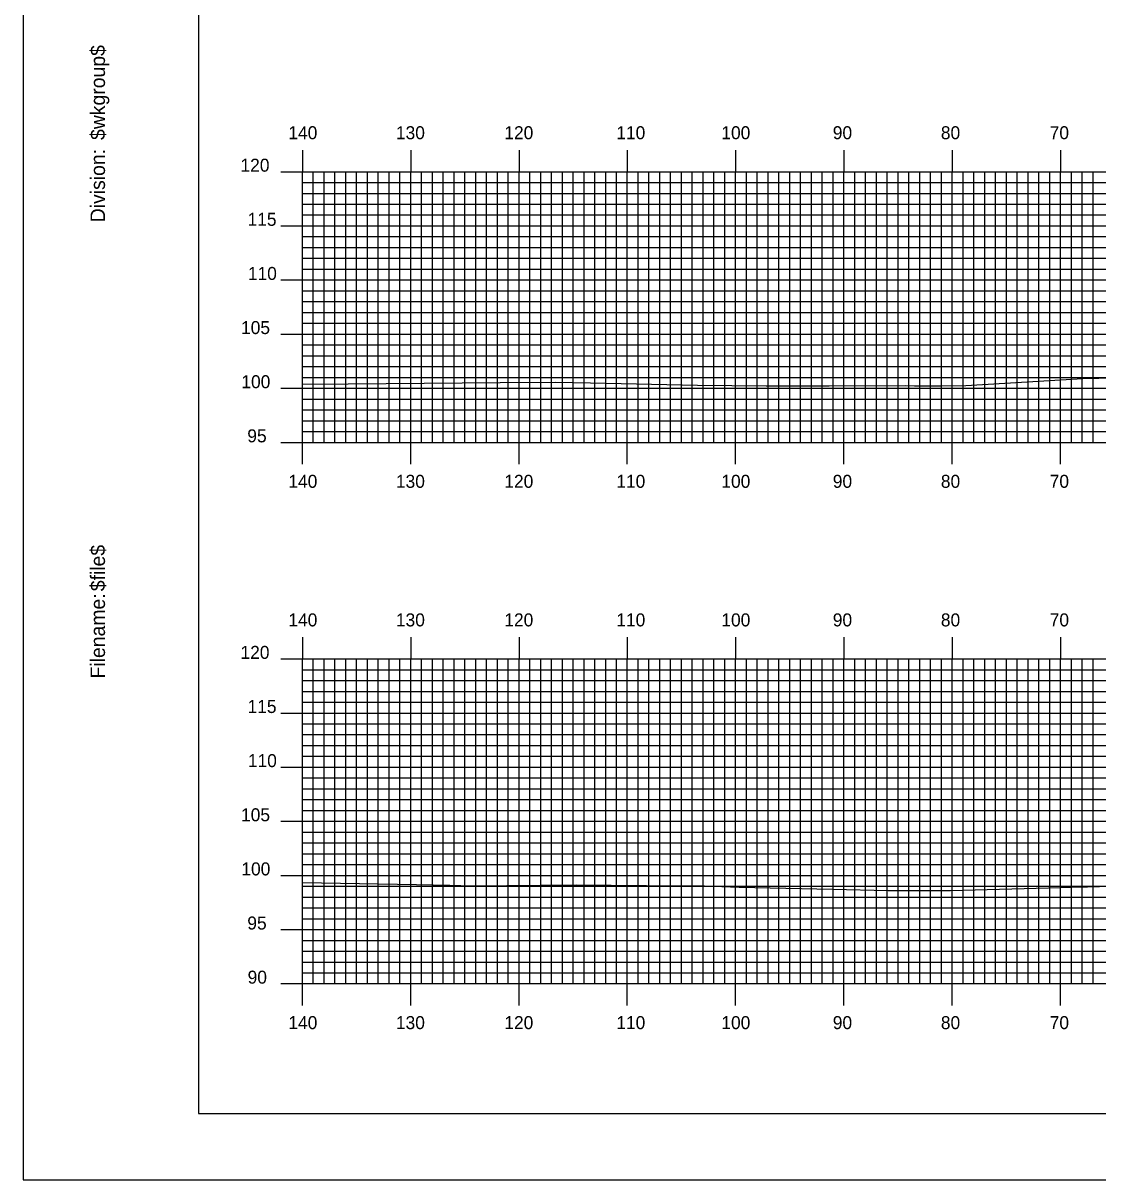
# Model space of a CAD drawing. Extents: x 1787763 to 1788106, y 442591 to 442811.
# Drawn here: x 1787762.8 to 1787862.1, y 442590.5 to 442697.4 of the extents above; entities that cross this region are included whole.
import ezdxf

# ---------------------------------------------------------------- set-up
doc = ezdxf.new("R2010")
doc.units = 0
for name, color, linetype in [('BORDER', 7, 'Continuous'), ('H_V ANNOTATION', 7, 'Continuous'), ('MAJOR', 7, 'Continuous'), ('MINOR', 7, 'Continuous'), ('PLOT BOUNDARY', 7, 'Continuous'), ('S_Roadway_Centerline', 7, 'Continuous')]:
    doc.layers.add(name, color=color, linetype=linetype)

msp = doc.modelspace()

# ---------------------------------------------------------------- linework, layer by layer
at = {"layer": 'BORDER'}
msp.add_lwpolyline([(1787779.02, 442596.67), (1788099.02, 442596.67), (1788099.02, 442806.67), (1787779.02, 442806.67)], close=True, dxfattribs=at)
at = {"layer": 'MAJOR'}
for p, q in [((1787788.62, 442685.67), (1787788.62, 442683.67)), ((1787798.62, 442685.67), (1787798.62, 442683.67)), ((1787808.62, 442685.67), (1787808.62, 442683.67)), ((1787818.62, 442685.67), (1787818.62, 442683.67)), ((1787828.62, 442685.67), (1787828.62, 442683.67)), ((1787838.62, 442685.67), (1787838.62, 442683.67)), ((1787848.62, 442685.67), (1787848.62, 442683.67)), ((1787858.62, 442685.67), (1787858.62, 442683.67)), ((1787786.61, 442683.67), (1787788.62, 442683.67)), ((1787788.62, 442683.67), (1788068.62, 442683.67)), ((1787788.62, 442658.67), (1787788.62, 442683.67)), ((1787788.62, 442658.67), (1787788.62, 442683.67)), ((1787788.62, 442683.67), (1788068.62, 442683.67)), ((1787798.62, 442658.67), (1787798.62, 442683.67)), ((1787808.62, 442658.67), (1787808.62, 442683.67)), ((1787818.62, 442658.67), (1787818.62, 442683.67)), ((1787828.62, 442658.67), (1787828.62, 442683.67)), ((1787838.62, 442658.67), (1787838.62, 442683.67)), ((1787848.62, 442658.67), (1787848.62, 442683.67)), ((1787858.62, 442658.67), (1787858.62, 442683.67)), ((1787786.61, 442678.67), (1787788.62, 442678.67)), ((1787788.62, 442678.67), (1788068.62, 442678.67)), ((1787786.61, 442673.67), (1787788.62, 442673.67)), ((1787788.62, 442673.67), (1788068.62, 442673.67)), ((1787786.61, 442668.67), (1787788.62, 442668.67)), ((1787788.62, 442668.67), (1788068.62, 442668.67)), ((1787786.61, 442663.67), (1787788.62, 442663.67)), ((1787788.62, 442663.67), (1788068.62, 442663.67)), ((1787786.61, 442658.67), (1787788.62, 442658.67)), ((1787788.62, 442658.67), (1788068.62, 442658.67)), ((1787788.62, 442658.67), (1788068.62, 442658.67)), ((1787788.62, 442656.66), (1787788.62, 442658.67)), ((1787798.62, 442656.66), (1787798.62, 442658.67)), ((1787808.62, 442656.66), (1787808.62, 442658.67)), ((1787818.62, 442656.66), (1787818.62, 442658.67)), ((1787828.62, 442656.66), (1787828.62, 442658.67)), ((1787838.62, 442656.66), (1787838.62, 442658.67)), ((1787848.62, 442656.66), (1787848.62, 442658.67)), ((1787858.62, 442656.66), (1787858.62, 442658.67)), ((1787788.62, 442640.67), (1787788.62, 442638.67)), ((1787798.62, 442640.67), (1787798.62, 442638.67)), ((1787808.62, 442640.67), (1787808.62, 442638.67)), ((1787818.62, 442640.67), (1787818.62, 442638.67)), ((1787828.62, 442640.67), (1787828.62, 442638.67)), ((1787838.62, 442640.67), (1787838.62, 442638.67)), ((1787848.62, 442640.67), (1787848.62, 442638.67)), ((1787858.62, 442640.67), (1787858.62, 442638.67)), ((1787786.61, 442638.67), (1787788.62, 442638.67)), ((1787788.62, 442638.67), (1788068.62, 442638.67)), ((1787788.62, 442608.67), (1787788.62, 442638.67)), ((1787788.62, 442608.67), (1787788.62, 442638.67)), ((1787788.62, 442638.67), (1788068.62, 442638.67)), ((1787798.62, 442608.67), (1787798.62, 442638.67)), ((1787808.62, 442608.67), (1787808.62, 442638.67)), ((1787818.62, 442608.67), (1787818.62, 442638.67)), ((1787828.62, 442608.67), (1787828.62, 442638.67)), ((1787838.62, 442608.67), (1787838.62, 442638.67)), ((1787848.62, 442608.67), (1787848.62, 442638.67)), ((1787858.62, 442608.67), (1787858.62, 442638.67)), ((1787786.61, 442633.67), (1787788.62, 442633.67)), ((1787788.62, 442633.67), (1788068.62, 442633.67)), ((1787786.61, 442628.67), (1787788.62, 442628.67)), ((1787788.62, 442628.67), (1788068.62, 442628.67)), ((1787786.61, 442623.67), (1787788.62, 442623.67)), ((1787788.62, 442623.67), (1788068.62, 442623.67)), ((1787786.61, 442618.67), (1787788.62, 442618.67)), ((1787788.62, 442618.67), (1788068.62, 442618.67)), ((1787786.61, 442613.67), (1787788.62, 442613.67)), ((1787788.62, 442613.67), (1788068.62, 442613.67)), ((1787786.61, 442608.67), (1787788.62, 442608.67)), ((1787788.62, 442608.67), (1788068.62, 442608.67)), ((1787788.62, 442608.67), (1788068.62, 442608.67)), ((1787788.62, 442606.66), (1787788.62, 442608.67)), ((1787798.62, 442606.66), (1787798.62, 442608.67)), ((1787808.62, 442606.66), (1787808.62, 442608.67)), ((1787818.62, 442606.66), (1787818.62, 442608.67)), ((1787828.62, 442606.66), (1787828.62, 442608.67)), ((1787838.62, 442606.66), (1787838.62, 442608.67)), ((1787848.62, 442606.66), (1787848.62, 442608.67)), ((1787858.62, 442606.66), (1787858.62, 442608.67))]:
    msp.add_line(p, q, dxfattribs=at)
at = {"layer": 'MINOR'}
for p, q in [((1787789.62, 442658.67), (1787789.62, 442683.67)), ((1787790.62, 442658.67), (1787790.62, 442683.67)), ((1787791.62, 442658.67), (1787791.62, 442683.67)), ((1787792.62, 442658.67), (1787792.62, 442683.67)), ((1787793.62, 442658.67), (1787793.62, 442683.67)), ((1787794.62, 442658.67), (1787794.62, 442683.67)), ((1787795.62, 442658.67), (1787795.62, 442683.67)), ((1787796.62, 442658.67), (1787796.62, 442683.67)), ((1787797.62, 442658.67), (1787797.62, 442683.67)), ((1787799.62, 442658.67), (1787799.62, 442683.67)), ((1787800.62, 442658.67), (1787800.62, 442683.67)), ((1787801.62, 442658.67), (1787801.62, 442683.67)), ((1787802.62, 442658.67), (1787802.62, 442683.67)), ((1787803.62, 442658.67), (1787803.62, 442683.67)), ((1787804.62, 442658.67), (1787804.62, 442683.67)), ((1787805.62, 442658.67), (1787805.62, 442683.67)), ((1787806.62, 442658.67), (1787806.62, 442683.67)), ((1787807.62, 442658.67), (1787807.62, 442683.67)), ((1787809.62, 442658.67), (1787809.62, 442683.67)), ((1787810.62, 442658.67), (1787810.62, 442683.67)), ((1787811.62, 442658.67), (1787811.62, 442683.67)), ((1787812.62, 442658.67), (1787812.62, 442683.67)), ((1787813.62, 442658.67), (1787813.62, 442683.67)), ((1787814.62, 442658.67), (1787814.62, 442683.67)), ((1787815.62, 442658.67), (1787815.62, 442683.67)), ((1787816.62, 442658.67), (1787816.62, 442683.67)), ((1787817.62, 442658.67), (1787817.62, 442683.67)), ((1787819.62, 442658.67), (1787819.62, 442683.67)), ((1787820.62, 442658.67), (1787820.62, 442683.67)), ((1787821.62, 442658.67), (1787821.62, 442683.67)), ((1787822.62, 442658.67), (1787822.62, 442683.67)), ((1787823.62, 442658.67), (1787823.62, 442683.67)), ((1787824.62, 442658.67), (1787824.62, 442683.67)), ((1787825.62, 442658.67), (1787825.62, 442683.67)), ((1787826.62, 442658.67), (1787826.62, 442683.67)), ((1787827.62, 442658.67), (1787827.62, 442683.67)), ((1787829.62, 442658.67), (1787829.62, 442683.67)), ((1787830.62, 442658.67), (1787830.62, 442683.67)), ((1787831.62, 442658.67), (1787831.62, 442683.67)), ((1787832.62, 442658.67), (1787832.62, 442683.67)), ((1787833.62, 442658.67), (1787833.62, 442683.67)), ((1787834.62, 442658.67), (1787834.62, 442683.67)), ((1787835.62, 442658.67), (1787835.62, 442683.67)), ((1787836.62, 442658.67), (1787836.62, 442683.67)), ((1787837.62, 442658.67), (1787837.62, 442683.67)), ((1787839.62, 442658.67), (1787839.62, 442683.67)), ((1787840.62, 442658.67), (1787840.62, 442683.67)), ((1787841.62, 442658.67), (1787841.62, 442683.67)), ((1787842.62, 442658.67), (1787842.62, 442683.67)), ((1787843.62, 442658.67), (1787843.62, 442683.67)), ((1787844.62, 442658.67), (1787844.62, 442683.67)), ((1787845.62, 442658.67), (1787845.62, 442683.67)), ((1787846.62, 442658.67), (1787846.62, 442683.67)), ((1787847.62, 442658.67), (1787847.62, 442683.67)), ((1787849.62, 442658.67), (1787849.62, 442683.67)), ((1787850.62, 442658.67), (1787850.62, 442683.67)), ((1787851.62, 442658.67), (1787851.62, 442683.67)), ((1787852.62, 442658.67), (1787852.62, 442683.67)), ((1787853.62, 442658.67), (1787853.62, 442683.67)), ((1787854.62, 442658.67), (1787854.62, 442683.67)), ((1787855.62, 442658.67), (1787855.62, 442683.67)), ((1787856.62, 442658.67), (1787856.62, 442683.67)), ((1787857.62, 442658.67), (1787857.62, 442683.67)), ((1787859.62, 442658.67), (1787859.62, 442683.67)), ((1787860.62, 442658.67), (1787860.62, 442683.67)), ((1787861.62, 442658.67), (1787861.62, 442683.67)), ((1787788.62, 442682.67), (1788068.62, 442682.67)), ((1787788.62, 442682.67), (1787790.62, 442682.67)), ((1787788.62, 442681.67), (1788068.62, 442681.67)), ((1787788.62, 442681.67), (1787790.62, 442681.67)), ((1787788.62, 442680.67), (1788068.62, 442680.67)), ((1787788.62, 442680.67), (1787790.62, 442680.67)), ((1787788.62, 442679.67), (1788068.62, 442679.67)), ((1787788.62, 442679.67), (1787790.62, 442679.67)), ((1787788.62, 442677.67), (1788068.62, 442677.67)), ((1787788.62, 442677.67), (1787790.62, 442677.67)), ((1787788.62, 442676.67), (1788068.62, 442676.67)), ((1787788.62, 442676.67), (1787790.62, 442676.67)), ((1787788.62, 442675.67), (1788068.62, 442675.67)), ((1787788.62, 442675.67), (1787790.62, 442675.67)), ((1787788.62, 442674.67), (1788068.62, 442674.67)), ((1787788.62, 442674.67), (1787790.62, 442674.67)), ((1787788.62, 442672.67), (1788068.62, 442672.67)), ((1787788.62, 442672.67), (1787790.62, 442672.67)), ((1787788.62, 442671.67), (1788068.62, 442671.67)), ((1787788.62, 442671.67), (1787790.62, 442671.67)), ((1787788.62, 442670.67), (1788068.62, 442670.67)), ((1787788.62, 442670.67), (1787790.62, 442670.67)), ((1787788.62, 442669.67), (1788068.62, 442669.67)), ((1787788.62, 442669.67), (1787790.62, 442669.67)), ((1787788.62, 442667.67), (1788068.62, 442667.67)), ((1787788.62, 442667.67), (1787790.62, 442667.67)), ((1787788.62, 442666.67), (1788068.62, 442666.67)), ((1787788.62, 442666.67), (1787790.62, 442666.67)), ((1787788.62, 442665.67), (1788068.62, 442665.67)), ((1787788.62, 442665.67), (1787790.62, 442665.67)), ((1787788.62, 442664.67), (1788068.62, 442664.67)), ((1787788.62, 442664.67), (1787790.62, 442664.67)), ((1787788.62, 442662.67), (1788068.62, 442662.67)), ((1787788.62, 442662.67), (1787790.62, 442662.67)), ((1787788.62, 442661.67), (1788068.62, 442661.67)), ((1787788.62, 442661.67), (1787790.62, 442661.67)), ((1787788.62, 442660.67), (1788068.62, 442660.67)), ((1787788.62, 442660.67), (1787790.62, 442660.67)), ((1787788.62, 442659.67), (1788068.62, 442659.67)), ((1787788.62, 442659.67), (1787790.62, 442659.67)), ((1787789.62, 442608.67), (1787789.62, 442638.67)), ((1787790.62, 442608.67), (1787790.62, 442638.67)), ((1787791.62, 442608.67), (1787791.62, 442638.67)), ((1787792.62, 442608.67), (1787792.62, 442638.67)), ((1787793.62, 442608.67), (1787793.62, 442638.67)), ((1787794.62, 442608.67), (1787794.62, 442638.67)), ((1787795.62, 442608.67), (1787795.62, 442638.67)), ((1787796.62, 442608.67), (1787796.62, 442638.67)), ((1787797.62, 442608.67), (1787797.62, 442638.67)), ((1787799.62, 442608.67), (1787799.62, 442638.67)), ((1787800.62, 442608.67), (1787800.62, 442638.67)), ((1787801.62, 442608.67), (1787801.62, 442638.67)), ((1787802.62, 442608.67), (1787802.62, 442638.67)), ((1787803.62, 442608.67), (1787803.62, 442638.67)), ((1787804.62, 442608.67), (1787804.62, 442638.67)), ((1787805.62, 442608.67), (1787805.62, 442638.67)), ((1787806.62, 442608.67), (1787806.62, 442638.67)), ((1787807.62, 442608.67), (1787807.62, 442638.67)), ((1787809.62, 442608.67), (1787809.62, 442638.67)), ((1787810.62, 442608.67), (1787810.62, 442638.67)), ((1787811.62, 442608.67), (1787811.62, 442638.67)), ((1787812.62, 442608.67), (1787812.62, 442638.67)), ((1787813.62, 442608.67), (1787813.62, 442638.67)), ((1787814.62, 442608.67), (1787814.62, 442638.67)), ((1787815.62, 442608.67), (1787815.62, 442638.67)), ((1787816.62, 442608.67), (1787816.62, 442638.67)), ((1787817.62, 442608.67), (1787817.62, 442638.67)), ((1787819.62, 442608.67), (1787819.62, 442638.67)), ((1787820.62, 442608.67), (1787820.62, 442638.67)), ((1787821.62, 442608.67), (1787821.62, 442638.67)), ((1787822.62, 442608.67), (1787822.62, 442638.67)), ((1787823.62, 442608.67), (1787823.62, 442638.67)), ((1787824.62, 442608.67), (1787824.62, 442638.67)), ((1787825.62, 442608.67), (1787825.62, 442638.67)), ((1787826.62, 442608.67), (1787826.62, 442638.67)), ((1787827.62, 442608.67), (1787827.62, 442638.67)), ((1787829.62, 442608.67), (1787829.62, 442638.67)), ((1787830.62, 442608.67), (1787830.62, 442638.67)), ((1787831.62, 442608.67), (1787831.62, 442638.67)), ((1787832.62, 442608.67), (1787832.62, 442638.67)), ((1787833.62, 442608.67), (1787833.62, 442638.67)), ((1787834.62, 442608.67), (1787834.62, 442638.67)), ((1787835.62, 442608.67), (1787835.62, 442638.67)), ((1787836.62, 442608.67), (1787836.62, 442638.67)), ((1787837.62, 442608.67), (1787837.62, 442638.67)), ((1787839.62, 442608.67), (1787839.62, 442638.67)), ((1787840.62, 442608.67), (1787840.62, 442638.67)), ((1787841.62, 442608.67), (1787841.62, 442638.67)), ((1787842.62, 442608.67), (1787842.62, 442638.67)), ((1787843.62, 442608.67), (1787843.62, 442638.67)), ((1787844.62, 442608.67), (1787844.62, 442638.67)), ((1787845.62, 442608.67), (1787845.62, 442638.67)), ((1787846.62, 442608.67), (1787846.62, 442638.67)), ((1787847.62, 442608.67), (1787847.62, 442638.67)), ((1787849.62, 442608.67), (1787849.62, 442638.67)), ((1787850.62, 442608.67), (1787850.62, 442638.67)), ((1787851.62, 442608.67), (1787851.62, 442638.67)), ((1787852.62, 442608.67), (1787852.62, 442638.67)), ((1787853.62, 442608.67), (1787853.62, 442638.67)), ((1787854.62, 442608.67), (1787854.62, 442638.67)), ((1787855.62, 442608.67), (1787855.62, 442638.67)), ((1787856.62, 442608.67), (1787856.62, 442638.67)), ((1787857.62, 442608.67), (1787857.62, 442638.67)), ((1787859.62, 442608.67), (1787859.62, 442638.67)), ((1787860.62, 442608.67), (1787860.62, 442638.67)), ((1787861.62, 442608.67), (1787861.62, 442638.67)), ((1787788.62, 442637.67), (1788068.62, 442637.67)), ((1787788.62, 442637.67), (1787790.62, 442637.67)), ((1787788.62, 442636.67), (1788068.62, 442636.67)), ((1787788.62, 442636.67), (1787790.62, 442636.67)), ((1787788.62, 442635.67), (1788068.62, 442635.67)), ((1787788.62, 442635.67), (1787790.62, 442635.67)), ((1787788.62, 442634.67), (1788068.62, 442634.67)), ((1787788.62, 442634.67), (1787790.62, 442634.67)), ((1787788.62, 442632.67), (1788068.62, 442632.67)), ((1787788.62, 442632.67), (1787790.62, 442632.67)), ((1787788.62, 442631.67), (1788068.62, 442631.67)), ((1787788.62, 442631.67), (1787790.62, 442631.67)), ((1787788.62, 442630.67), (1788068.62, 442630.67)), ((1787788.62, 442630.67), (1787790.62, 442630.67)), ((1787788.62, 442629.67), (1788068.62, 442629.67)), ((1787788.62, 442629.67), (1787790.62, 442629.67)), ((1787788.62, 442627.67), (1788068.62, 442627.67)), ((1787788.62, 442627.67), (1787790.62, 442627.67)), ((1787788.62, 442626.67), (1788068.62, 442626.67)), ((1787788.62, 442626.67), (1787790.62, 442626.67)), ((1787788.62, 442625.67), (1788068.62, 442625.67)), ((1787788.62, 442625.67), (1787790.62, 442625.67)), ((1787788.62, 442624.67), (1788068.62, 442624.67)), ((1787788.62, 442624.67), (1787790.62, 442624.67)), ((1787788.62, 442622.67), (1788068.62, 442622.67)), ((1787788.62, 442622.67), (1787790.62, 442622.67)), ((1787788.62, 442621.67), (1788068.62, 442621.67)), ((1787788.62, 442621.67), (1787790.62, 442621.67)), ((1787788.62, 442620.67), (1788068.62, 442620.67)), ((1787788.62, 442620.67), (1787790.62, 442620.67)), ((1787788.62, 442619.67), (1788068.62, 442619.67)), ((1787788.62, 442619.67), (1787790.62, 442619.67)), ((1787788.62, 442617.67), (1788068.62, 442617.67)), ((1787788.62, 442617.67), (1787790.62, 442617.67)), ((1787788.62, 442616.67), (1788068.62, 442616.67)), ((1787788.62, 442616.67), (1787790.62, 442616.67)), ((1787788.62, 442615.67), (1788068.62, 442615.67)), ((1787788.62, 442615.67), (1787790.62, 442615.67)), ((1787788.62, 442614.67), (1788068.62, 442614.67)), ((1787788.62, 442614.67), (1787790.62, 442614.67)), ((1787788.62, 442612.67), (1788068.62, 442612.67)), ((1787788.62, 442612.67), (1787790.62, 442612.67)), ((1787788.62, 442611.67), (1788068.62, 442611.67)), ((1787788.62, 442611.67), (1787790.62, 442611.67)), ((1787788.62, 442610.67), (1788068.62, 442610.67)), ((1787788.62, 442610.67), (1787790.62, 442610.67)), ((1787788.62, 442609.67), (1788068.62, 442609.67)), ((1787788.62, 442609.67), (1787790.62, 442609.67))]:
    msp.add_line(p, q, dxfattribs=at)
at = {"layer": 'PLOT BOUNDARY'}
msp.add_lwpolyline([(1787762.83, 442590.55), (1788102.83, 442590.55), (1788102.83, 442810.55), (1787762.83, 442810.55)], close=True, dxfattribs=at)
at = {"layer": 'S_Roadway_Centerline'}
for points in [[(1787788.62, 442664.05), (1787792.85, 442664.07), (1787806.88, 442664.2), (1787812.01, 442664.22), (1787815.23, 442664.18), (1787825.11, 442663.94), (1787831.44, 442663.9), (1787837.27, 442663.89), (1787844.35, 442663.91), (1787845.13, 442663.89), (1787847.53, 442663.88), (1787849.87, 442663.93), (1787860.67, 442664.56), (1787869.64, 442664.74)], [(1787788.62, 442618.02), (1787799.14, 442617.82), (1787802.23, 442617.77), (1787804.3, 442617.72), (1787813.91, 442617.81), (1787823.63, 442617.71), (1787825.76, 442617.7), (1787828.96, 442617.59), (1787837.55, 442617.41), (1787842.7, 442617.27), (1787846.37, 442617.26), (1787848.46, 442617.26), (1787858.64, 442617.54), (1787860.54, 442617.6), (1787861.11, 442617.62), (1787861.36, 442617.63), (1787862.19, 442617.62)]]:
    msp.add_lwpolyline(points, dxfattribs=at)

# ---------------------------------------------------------------- texts
at = {"layer": 'BORDER'}
for s, p in [('$wkgroup$', (1787770.39, 442686.6)), ('Division:', (1787770.39, 442679)), ('$file$', (1787770.39, 442644.92)), ('Filename:', (1787770.39, 442636.86))]:
    msp.add_text(s, height=1.339, rotation=90, dxfattribs=at).set_placement(p)
at = {"layer": 'H_V ANNOTATION'}
for s, p in [('140', (1787787.32, 442686.67)), ('130', (1787797.25, 442686.67)), ('120', (1787807.26, 442686.67)), ('110', (1787817.6, 442686.67)), ('100', (1787827.3, 442686.67)), ('90', (1787837.59, 442686.67)), ('80', (1787847.57, 442686.67)), ('70', (1787857.62, 442686.67)), ('120', (1787782.9, 442683.67)), ('115', (1787783.55, 442678.67)), ('110', (1787783.58, 442673.67)), ('105', (1787782.95, 442668.67)), ('100', (1787782.98, 442663.67)), ('95', (1787783.53, 442658.67)), ('140', (1787787.32, 442654.47)), ('130', (1787797.25, 442654.47)), ('120', (1787807.26, 442654.47)), ('110', (1787817.6, 442654.47)), ('100', (1787827.3, 442654.47)), ('90', (1787837.59, 442654.47)), ('80', (1787847.57, 442654.47)), ('70', (1787857.62, 442654.47)), ('140', (1787787.32, 442641.67)), ('130', (1787797.25, 442641.67)), ('120', (1787807.26, 442641.67)), ('110', (1787817.6, 442641.67)), ('100', (1787827.3, 442641.67)), ('90', (1787837.59, 442641.67)), ('80', (1787847.57, 442641.67)), ('70', (1787857.62, 442641.67)), ('120', (1787782.9, 442638.67)), ('115', (1787783.55, 442633.67)), ('110', (1787783.58, 442628.67)), ('105', (1787782.95, 442623.67)), ('100', (1787782.98, 442618.67)), ('95', (1787783.53, 442613.67)), ('90', (1787783.56, 442608.67)), ('140', (1787787.32, 442604.47)), ('130', (1787797.25, 442604.47)), ('120', (1787807.26, 442604.47)), ('110', (1787817.6, 442604.47)), ('100', (1787827.3, 442604.47)), ('90', (1787837.59, 442604.47)), ('80', (1787847.57, 442604.47)), ('70', (1787857.62, 442604.47))]:
    msp.add_text(s, height=1.2, dxfattribs=at).set_placement(p)
at = {"layer": 'MAJOR'}
for p in [(1787788.61, 442658.67), (1787788.61, 442608.67)]:
    msp.add_text('-', height=0.012, dxfattribs=at).set_placement(p)

doc.saveas('drawing.dxf')
